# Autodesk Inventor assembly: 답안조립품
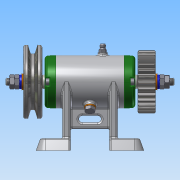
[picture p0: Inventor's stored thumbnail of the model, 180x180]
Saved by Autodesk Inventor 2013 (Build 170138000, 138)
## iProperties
Created: 2016-07
Part Number: 답안조립품
Document SubType Name: Assembly
Designer: Administrator
Author: Administrator
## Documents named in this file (16)
- C:\Users\Administrator\Desktop\460708V1004\답안조립품.iam
- C:\Users\Administrator\Desktop\460708V1004\본체.ipt
- C:\Users\Administrator\Desktop\460708V1004\V벨트풀리.ipt
- C:\Users\Administrator\Desktop\460708V1004\너트 M 8.ipt
- C:\Users\Administrator\Desktop\460708V1004\니플 M 6 x 0.75.ipt
- C:\Users\Administrator\Desktop\460708V1004\베어링 15 x 32 x 9.ipt
- C:\Users\Administrator\Desktop\460708V1004\볼트 M 6 x 8.ipt
- C:\Users\Administrator\Desktop\460708V1004\볼트 M4 x 12.ipt
- C:\Users\Administrator\Desktop\460708V1004\스퍼기어.ipt
- C:\Users\Administrator\Desktop\460708V1004\스프링와셔 8.ipt
- C:\Users\Administrator\Desktop\460708V1004\오일 실 15 25 7.ipt
- C:\Users\Administrator\Desktop\460708V1004\와셔 6x11.5.ipt
- C:\Users\Administrator\Desktop\460708V1004\와셔 8x17.ipt
- C:\Users\Administrator\Desktop\460708V1004\축.ipt
- C:\Users\Administrator\Desktop\460708V1004\커버.ipt
- C:\Users\Administrator\Desktop\460708V1004\키 3 x 3 x 12.ipt
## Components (11 placed, 3 different names)
1. V벨트풀리:1
2. KS B 2023 6002 - 15 x 32 x 9:1
3. KS B 2023 6002 - 15 x 32 x 9:2
4. ISO 4762 M4 x 12:2
5. ISO 4762 M4 x 12:3
6. ISO 4762 M4 x 12:4
7. ISO 4762 M4 x 12:5
8. ISO 4762 M4 x 12:1
9. ISO 4762 M4 x 12:6
10. ISO 4762 M4 x 12:7
11. ISO 4762 M4 x 12:8
